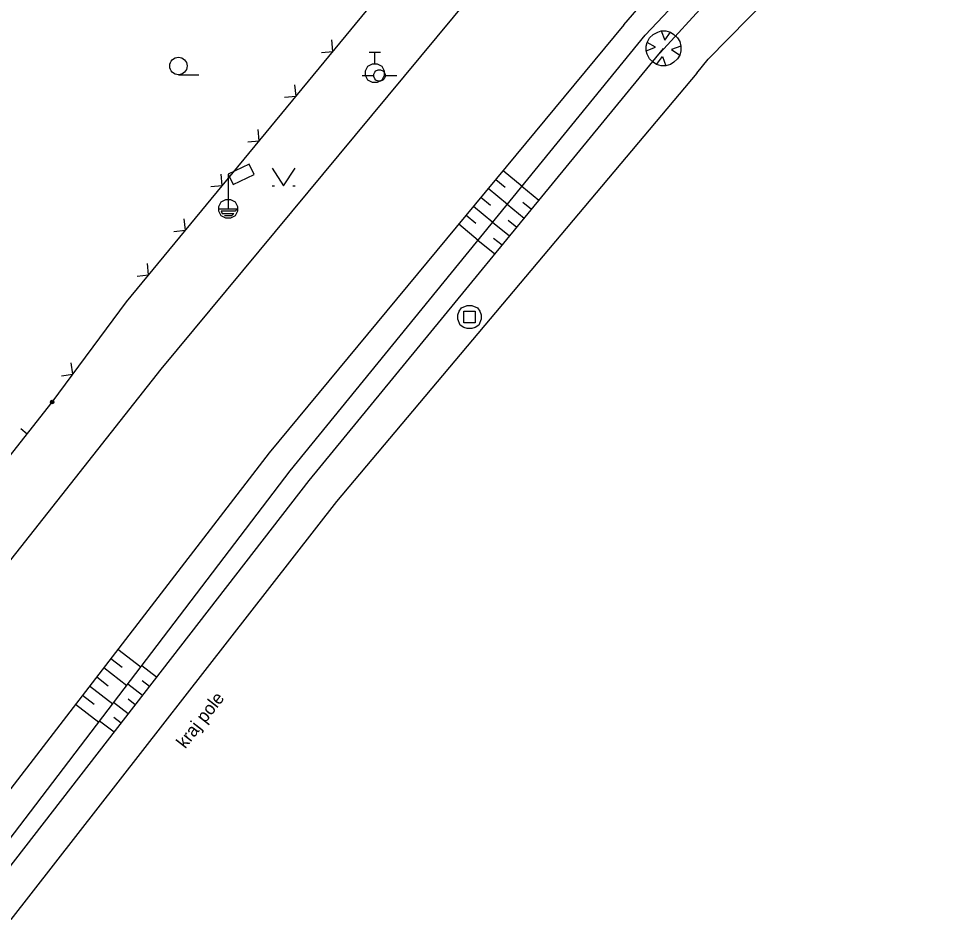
# Model space of a CAD drawing. Extents: x -559554 to -559082, y -1075950 to -1075150.
# Drawn here: x -559329.02 to -559289.23, y -1075601.86 to -1075563 of the extents above; entities that cross this region are included whole.
import ezdxf

# ---------------------------------------------------------------- set-up
doc = ezdxf.new("R2010")
doc.units = 0
doc.layers.add('kl', color=7, linetype='Continuous')

msp = doc.modelspace()

# ---------------------------------------------------------------- linework, layer by layer
at = {"layer": 'kl'}
for p, q in [((-559302.897, -1075563.272), (-559292.26, -1075551.03)), ((-559301.978, -1075563.716), (-559291.1, -1075552.2)), ((-559301.483, -1075564.656), (-559290.55, -1075552.69)), ((-559299.259, -1075564.757), (-559289.23, -1075554.52)), ((-559324.36, -1075575.22), (-559310.64, -1075558.6)), ((-559322.854, -1075578.126), (-559307.453, -1075559.571)), ((-559302.897, -1075563.272), (-559318.199, -1075581.732)), ((-559301.433, -1075563.591), (-559301.283, -1075563.541)), ((-559301.283, -1075563.541), (-559301.083, -1075563.541)), ((-559301.283, -1075563.541), (-559301.133, -1075563.941)), ((-559301.083, -1075563.541), (-559300.883, -1075563.591)), ((-559317.289, -1075582.503), (-559301.978, -1075563.716)), ((-559315.447, -1075564.423), (-559315.494, -1075563.93)), ((-559301.883, -1075564.041), (-559301.783, -1075563.841)), ((-559301.783, -1075563.841), (-559301.633, -1075563.691)), ((-559301.633, -1075563.691), (-559301.433, -1075563.591)), ((-559301.133, -1075563.941), (-559300.883, -1075563.591)), ((-559300.883, -1075563.591), (-559300.733, -1075563.691)), ((-559300.733, -1075563.691), (-559300.583, -1075563.841)), ((-559300.583, -1075563.841), (-559300.483, -1075563.991)), ((-559316.47, -1075582.927), (-559301.183, -1075564.291)), ((-559301.933, -1075564.191), (-559301.883, -1075564.041)), ((-559301.933, -1075564.391), (-559301.933, -1075564.191)), ((-559301.933, -1075564.391), (-559301.533, -1075564.241)), ((-559301.533, -1075564.241), (-559301.883, -1075564.041)), ((-559300.433, -1075564.191), (-559300.833, -1075564.341)), ((-559300.833, -1075564.341), (-559300.483, -1075564.591)), ((-559300.483, -1075563.991), (-559300.433, -1075564.191)), ((-559300.433, -1075564.191), (-559300.433, -1075564.391)), ((-559315.94, -1075564.47), (-559315.447, -1075564.423)), ((-559313.89, -1075564.46), (-559313.39, -1075564.46)), ((-559313.64, -1075564.96), (-559313.64, -1075564.46)), ((-559301.883, -1075564.541), (-559301.933, -1075564.391)), ((-559301.783, -1075564.741), (-559301.883, -1075564.541)), ((-559301.633, -1075564.891), (-559301.783, -1075564.741)), ((-559301.483, -1075564.991), (-559301.233, -1075564.641)), ((-559301.233, -1075564.641), (-559301.083, -1075565.041)), ((-559300.583, -1075564.741), (-559300.733, -1075564.891)), ((-559300.483, -1075564.591), (-559300.583, -1075564.741)), ((-559300.433, -1075564.391), (-559300.483, -1075564.591)), ((-559314.04, -1075565.26), (-559313.94, -1075565.06)), ((-559313.94, -1075565.06), (-559313.74, -1075564.96)), ((-559313.74, -1075564.96), (-559313.54, -1075564.96)), ((-559313.54, -1075564.96), (-559313.34, -1075565.06)), ((-559313.34, -1075565.06), (-559313.24, -1075565.26)), ((-559301.483, -1075564.991), (-559301.633, -1075564.891)), ((-559301.283, -1075565.041), (-559301.483, -1075564.991)), ((-559301.083, -1075565.041), (-559301.283, -1075565.041)), ((-559300.883, -1075564.991), (-559301.083, -1075565.041)), ((-559300.733, -1075564.891), (-559300.883, -1075564.991)), ((-559299.748, -1075565.359), (-559299.259, -1075564.757)), ((-559322.113, -1075565.425), (-559321.238, -1075565.425)), ((-559299.748, -1075565.359), (-559315.296, -1075583.828)), ((-559314.19, -1075565.46), (-559313.69, -1075565.46)), ((-559314.04, -1075565.46), (-559314.04, -1075565.26)), ((-559313.94, -1075565.66), (-559314.04, -1075565.46)), ((-559313.69, -1075565.41), (-559313.64, -1075565.31)), ((-559313.69, -1075565.51), (-559313.69, -1075565.41)), ((-559313.64, -1075565.61), (-559313.69, -1075565.51)), ((-559313.64, -1075565.31), (-559313.59, -1075565.26)), ((-559313.59, -1075565.26), (-559313.49, -1075565.21)), ((-559313.49, -1075565.21), (-559313.39, -1075565.21)), ((-559313.39, -1075565.21), (-559313.29, -1075565.26)), ((-559313.24, -1075565.46), (-559313.34, -1075565.66)), ((-559313.29, -1075565.26), (-559313.24, -1075565.31)), ((-559313.24, -1075565.26), (-559313.24, -1075565.46)), ((-559313.24, -1075565.31), (-559313.19, -1075565.41)), ((-559313.19, -1075565.51), (-559313.24, -1075565.61)), ((-559313.19, -1075565.41), (-559313.19, -1075565.51)), ((-559313.19, -1075565.46), (-559312.69, -1075565.46)), ((-559317.038, -1075566.351), (-559317.086, -1075565.858)), ((-559313.74, -1075565.76), (-559313.94, -1075565.66)), ((-559313.54, -1075565.76), (-559313.74, -1075565.76)), ((-559313.59, -1075565.66), (-559313.64, -1075565.61)), ((-559313.49, -1075565.71), (-559313.59, -1075565.66)), ((-559313.34, -1075565.66), (-559313.54, -1075565.76)), ((-559313.39, -1075565.71), (-559313.49, -1075565.71)), ((-559313.29, -1075565.66), (-559313.39, -1075565.71)), ((-559313.24, -1075565.61), (-559313.29, -1075565.66)), ((-559317.531, -1075566.398), (-559317.038, -1075566.351)), ((-559318.63, -1075568.279), (-559318.677, -1075567.786)), ((-559319.123, -1075568.326), (-559318.63, -1075568.279)), ((-559319.067, -1075569.279), (-559319.97, -1075569.71)), ((-559318.852, -1075569.731), (-559319.067, -1075569.279)), ((-559318.075, -1075569.462), (-559317.575, -1075570.212)), ((-559317.575, -1075570.212), (-559317.075, -1075569.462)), ((-559320.221, -1075570.207), (-559320.269, -1075569.714)), ((-559319.97, -1075569.71), (-559319.97, -1075571.21)), ((-559319.97, -1075569.71), (-559319.755, -1075570.161)), ((-559319.755, -1075570.161), (-559318.852, -1075569.731)), ((-559308.104, -1075569.554), (-559307.288, -1075570.231)), ((-559320.714, -1075570.254), (-559320.221, -1075570.207)), ((-559318.075, -1075570.212), (-559317.975, -1075570.212)), ((-559317.175, -1075570.212), (-559317.075, -1075570.212)), ((-559308.423, -1075569.939), (-559308.014, -1075570.279)), ((-559306.563, -1075570.849), (-559307.299, -1075570.245)), ((-559309.062, -1075570.709), (-559308.649, -1075571.052)), ((-559308.743, -1075570.324), (-559307.919, -1075571.006)), ((-559320.37, -1075571.11), (-559320.27, -1075570.91)), ((-559320.37, -1075571.31), (-559320.37, -1075571.11)), ((-559320.27, -1075570.91), (-559320.07, -1075570.81)), ((-559320.07, -1075570.81), (-559319.87, -1075570.81)), ((-559319.87, -1075570.81), (-559319.67, -1075570.91)), ((-559319.67, -1075570.91), (-559319.57, -1075571.11)), ((-559319.57, -1075571.11), (-559319.57, -1075571.31)), ((-559309.381, -1075571.094), (-559308.551, -1075571.782)), ((-559307.197, -1075571.622), (-559307.931, -1075571.02)), ((-559306.88, -1075571.236), (-559307.248, -1075570.934)), ((-559320.37, -1075571.21), (-559319.57, -1075571.21)), ((-559320.27, -1075571.51), (-559320.37, -1075571.31)), ((-559319.67, -1075571.31), (-559320.27, -1075571.31)), ((-559320.27, -1075571.31), (-559320.22, -1075571.41)), ((-559320.22, -1075571.41), (-559319.72, -1075571.41)), ((-559319.72, -1075571.41), (-559319.82, -1075571.51)), ((-559319.57, -1075571.21), (-559319.67, -1075571.31)), ((-559319.57, -1075571.31), (-559319.67, -1075571.51)), ((-559309.7, -1075571.479), (-559309.283, -1075571.824)), ((-559321.813, -1075572.135), (-559321.86, -1075571.642)), ((-559320.07, -1075571.61), (-559320.27, -1075571.51)), ((-559319.82, -1075571.51), (-559320.12, -1075571.51)), ((-559319.87, -1075571.61), (-559320.07, -1075571.61)), ((-559319.67, -1075571.51), (-559319.87, -1075571.61)), ((-559310.019, -1075571.864), (-559309.183, -1075572.557)), ((-559307.831, -1075572.396), (-559308.563, -1075571.796)), ((-559307.514, -1075572.009), (-559307.88, -1075571.709)), ((-559322.306, -1075572.182), (-559321.813, -1075572.135)), ((-559308.465, -1075573.169), (-559309.194, -1075572.571)), ((-559308.148, -1075572.782), (-559308.513, -1075572.483)), ((-559323.405, -1075574.063), (-559323.452, -1075573.57)), ((-559323.897, -1075574.11), (-559323.405, -1075574.063)), ((-559327.56, -1075579.54), (-559324.36, -1075575.22)), ((-559310.005, -1075575.624), (-559309.905, -1075575.474)), ((-559309.905, -1075575.474), (-559309.655, -1075575.374)), ((-559309.655, -1075575.374), (-559309.455, -1075575.374)), ((-559309.455, -1075575.374), (-559309.205, -1075575.474)), ((-559309.205, -1075575.474), (-559309.105, -1075575.624)), ((-559310.055, -1075575.774), (-559310.005, -1075575.624)), ((-559310.055, -1075575.974), (-559310.055, -1075575.774)), ((-559309.805, -1075575.624), (-559309.305, -1075575.624)), ((-559309.805, -1075576.124), (-559309.805, -1075575.624)), ((-559309.305, -1075575.624), (-559309.305, -1075576.124)), ((-559309.105, -1075575.624), (-559309.055, -1075575.774)), ((-559309.055, -1075575.774), (-559309.055, -1075575.974)), ((-559309.955, -1075576.224), (-559310.055, -1075575.974)), ((-559309.805, -1075576.324), (-559309.955, -1075576.224)), ((-559309.305, -1075576.124), (-559309.805, -1075576.124)), ((-559309.155, -1075576.224), (-559309.305, -1075576.324)), ((-559309.055, -1075575.974), (-559309.155, -1075576.224)), ((-559309.655, -1075576.374), (-559309.805, -1075576.324)), ((-559309.455, -1075576.374), (-559309.655, -1075576.374)), ((-559309.305, -1075576.324), (-559309.455, -1075576.374)), ((-559326.667, -1075578.334), (-559326.74, -1075577.845)), ((-559329.51, -1075586.55), (-559322.854, -1075578.126)), ((-559327.156, -1075578.407), (-559326.667, -1075578.334)), ((-559329.57, -1075582.1), (-559327.56, -1075579.54)), ((-559327.61, -1075579.515), (-559327.61, -1075579.565)), ((-559327.61, -1075579.565), (-559327.585, -1075579.59)), ((-559327.585, -1075579.59), (-559327.585, -1075579.49)), ((-559327.585, -1075579.49), (-559327.56, -1075579.49)), ((-559327.56, -1075579.49), (-559327.56, -1075579.59)), ((-559327.56, -1075579.59), (-559327.535, -1075579.59)), ((-559327.535, -1075579.59), (-559327.535, -1075579.49)), ((-559327.535, -1075579.49), (-559327.51, -1075579.515)), ((-559327.51, -1075579.515), (-559327.51, -1075579.565)), ((-559328.643, -1075580.92), (-559328.918, -1075580.704)), ((-559318.199, -1075581.732), (-559332.258, -1075599.97)), ((-559331.129, -1075600.662), (-559317.289, -1075582.503)), ((-559330.567, -1075601.091), (-559316.47, -1075582.927)), ((-559315.296, -1075583.828), (-559329.35, -1075601.857)), ((-559324.727, -1075590.2), (-559323.737, -1075590.963)), ((-559325.032, -1075590.596), (-559324.536, -1075590.979)), ((-559325.337, -1075590.992), (-559324.343, -1075591.759)), ((-559323.054, -1075591.41), (-559323.697, -1075590.911)), ((-559325.642, -1075591.388), (-559325.144, -1075591.772)), ((-559325.948, -1075591.784), (-559324.949, -1075592.554)), ((-559323.667, -1075592.2), (-559324.303, -1075591.707)), ((-559323.361, -1075591.805), (-559323.68, -1075591.557)), ((-559326.253, -1075592.18), (-559325.753, -1075592.566)), ((-559326.558, -1075592.576), (-559325.555, -1075593.349)), ((-559324.28, -1075592.99), (-559324.909, -1075592.502)), ((-559323.974, -1075592.595), (-559324.29, -1075592.35)), ((-559324.893, -1075593.78), (-559325.516, -1075593.297)), ((-559324.587, -1075593.385), (-559324.9, -1075593.142))]:
    msp.add_line(p, q, dxfattribs=at)
for centre, radius in [((-559322.114, -1075565.051), 0.375), ((-559327.56, -1075579.54), 0.075)]:
    msp.add_circle(centre, radius, dxfattribs=at)

# ---------------------------------------------------------------- texts
msp.add_text('kraj pole', height=0.5525, rotation=52.0616, dxfattribs=at).set_placement((-559321.82, -1075594.52))

doc.saveas('drawing.dxf')
